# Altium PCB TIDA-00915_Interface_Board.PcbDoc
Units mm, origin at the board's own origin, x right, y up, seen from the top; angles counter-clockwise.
Board outline 75 x 27 mm, 4 copper layers (Top Layer, Signal Layer 1, Signal Layer 2, Bottom Layer), stack 0.8 mm thick; 16 components, 9 nets, 149 pads, 23 vias.
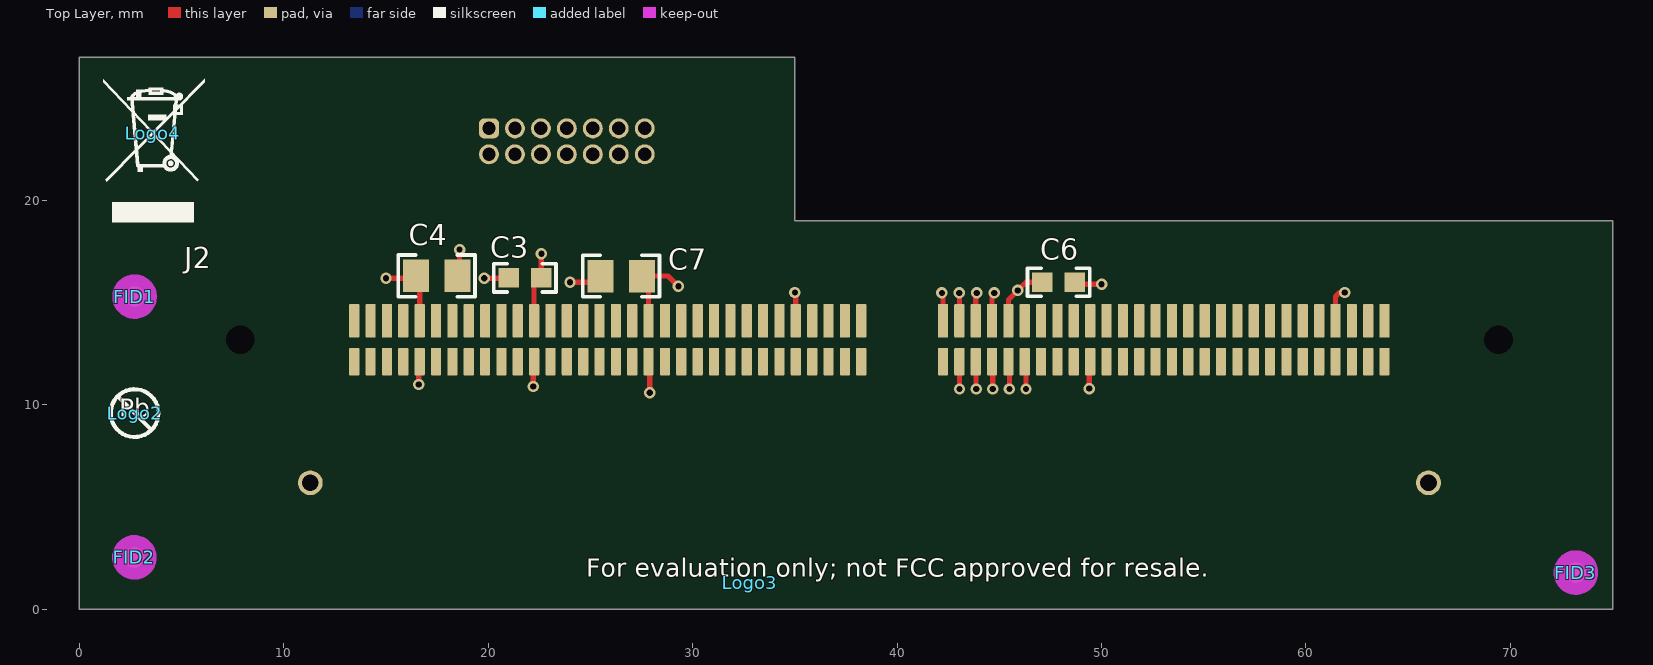
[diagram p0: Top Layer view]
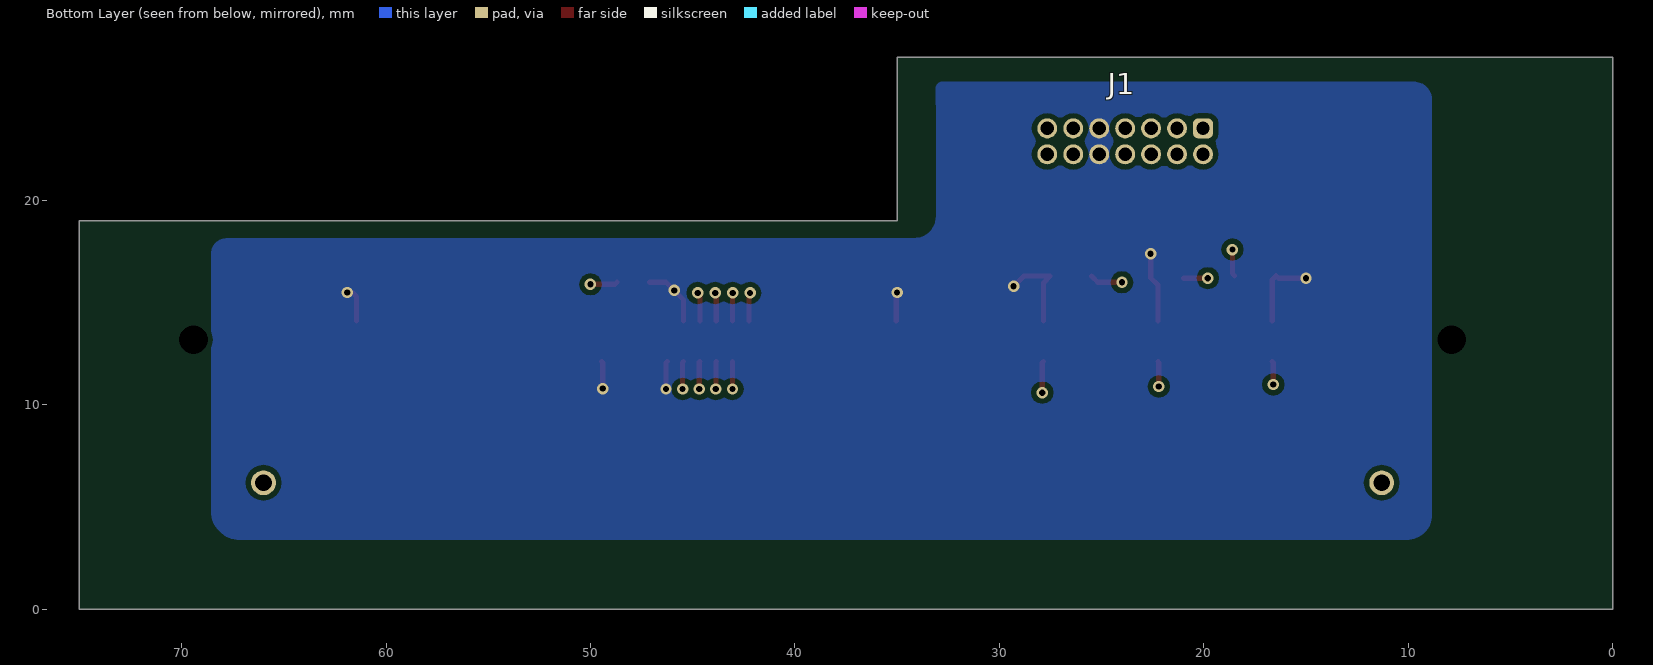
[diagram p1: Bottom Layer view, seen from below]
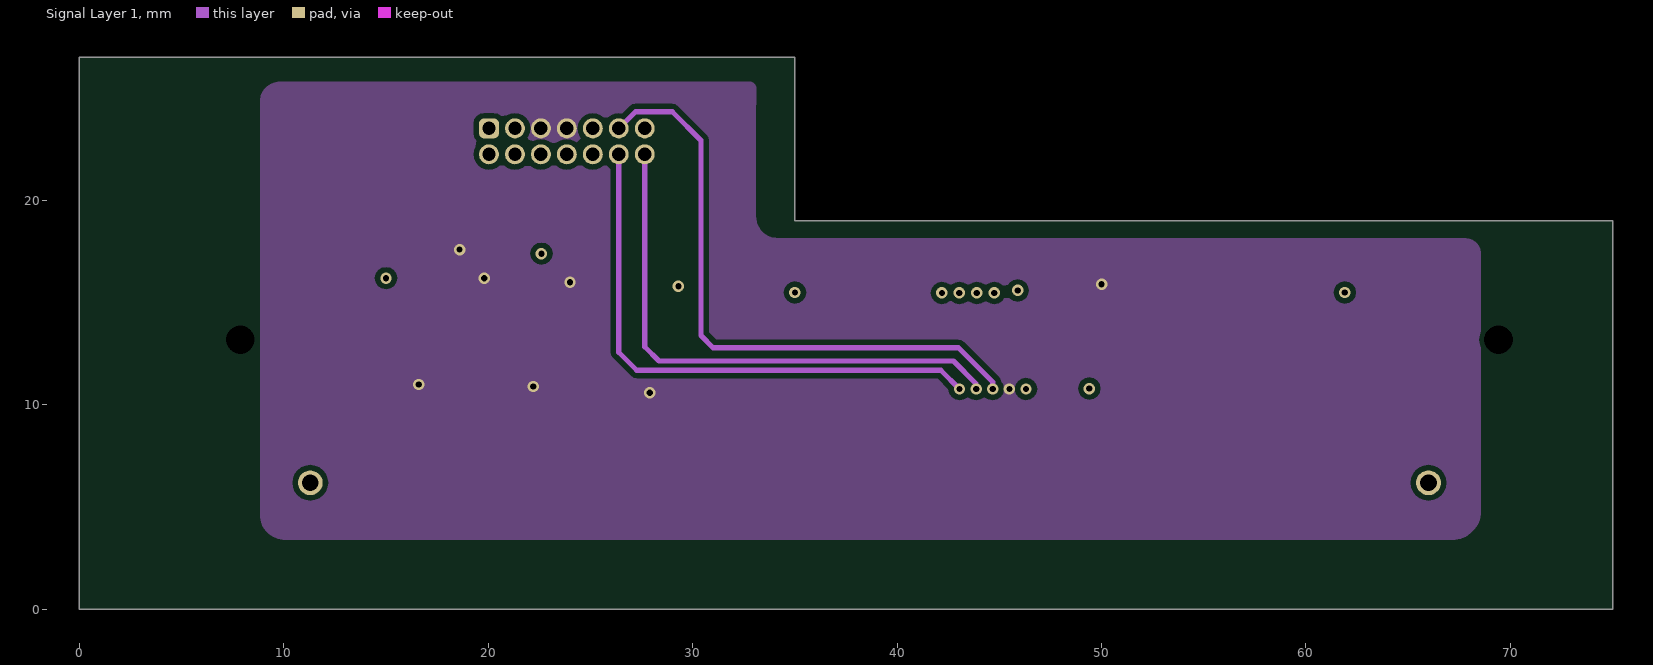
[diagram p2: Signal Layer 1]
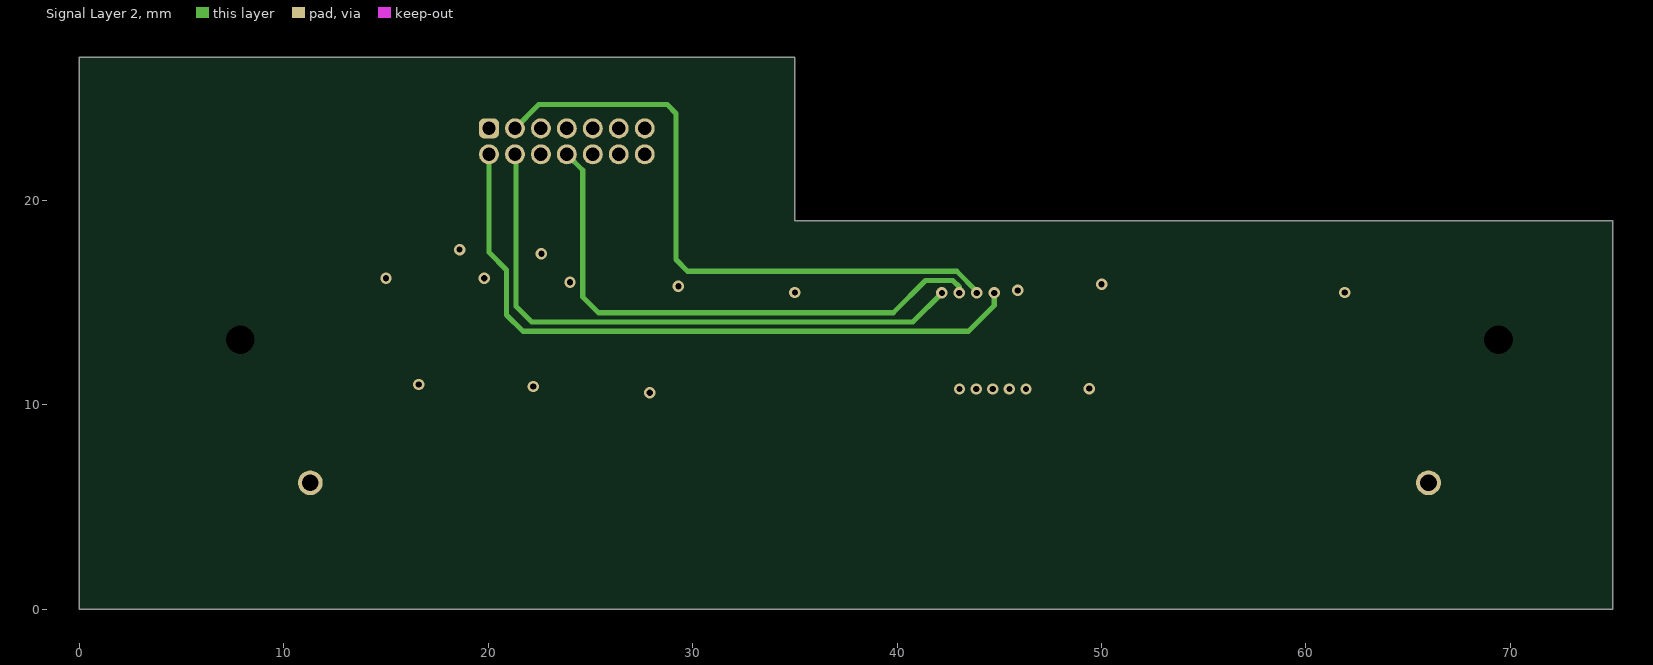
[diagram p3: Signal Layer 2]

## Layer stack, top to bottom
Top Solder: solder mask 0.0102, Solder Resist, Dk 3.5
Top Layer: signal copper 0.07
Dielectric 3: dielectric 0.16, FR-4  High Tg, Dk 4.2
Signal Layer 1: signal copper 0.07
Dielectric1: core 0.2, FR-4  High Tg, Dk 4.8
Signal Layer 2: signal copper 0.07
Dielectric 2: dielectric 0.16, FR-4  High Tg, Dk 4.2
Bottom Layer: signal copper 0.07
Bottom Solder: solder mask 0.0102, Solder Resist, Dk 3.5

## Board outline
0,0 75,0 75,19 35,19 35,27 0,27

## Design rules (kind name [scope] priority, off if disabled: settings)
AcuteAngle [All] p1: minimum=4.50000000000000E+0001 checktracksonly=FALSE
AssemblyTestPointUsage [All] p1: valid=2
BoardOutlineClearance BoardOutlineClearance_MountingHoles [OnCopper and InComponentClass('Mounting Holes')] p1: gap=1.016 ignorepadtopadclearanceinfootprint=FALSE
BoardOutlineClearance BoardOutlineClearance_Poly [OnCopper and IsPoly] p2: gap=0.635 ignorepadtopadclearanceinfootprint=FALSE
BoardOutlineClearance [OnCopper and Not InComponentClass('Logo') and not InComponentClass('FiducialMark') and not InRegion(1000,500,4000,800) and not InPoly] p3: gap=0.8 ignorepadtopadclearanceinfootprint=FALSE
Clearance Clearance_Keepouts [((IsTrack Or IsArc) And Not InPoly) And IsFree and IsKeepOut vs ((IsTrack Or IsArc) And Not InPoly) And IsFree and IsKeepOut] p1: gap=0 ignorepadtopadclearanceinfootprint=FALSE
Clearance Clearance_Poly [InPolygon] p2: gap=0.254 ignorepadtopadclearanceinfootprint=FALSE except(0: Arc-Hole Track-Hole SMDPad-Hole THPad-Hole Via-Hole Fill-Hole Poly-Hole Region-Hole Text-Hole)
Clearance Clearance_FiducialMark [IsKeepOut and InComponentClass('FiducialMark') vs IsPad and InComponentClass('FiducialMark')] p3: gap=0 ignorepadtopadclearanceinfootprint=FALSE
Clearance [All] p4: gap=0.2 ignorepadtopadclearanceinfootprint=FALSE except(0: Arc-Hole Track-Hole SMDPad-Hole THPad-Hole Via-Hole Fill-Hole Poly-Hole Region-Hole Text-Hole)
ComponentClearance ComponentClearance_MountingHoles_FiducialMarks [InComponentClass('Mounting Holes') vs InComponentClass('FiducialMark')] p1: gap=1.27 collisioncheckmode=3 verticalgap=0.254 showdistances=FALSE
ComponentClearance ComponentClearance_Shunt [InComponentClass('Header') vs InComponentClass('Shunt')] p2: gap=0 collisioncheckmode=3 verticalgap=0 showdistances=FALSE
ComponentClearance ComponentClearance_Logo [InComponentClass('Logo')] p3: gap=1.27 collisioncheckmode=3 verticalgap=0.254 showdistances=FALSE
ComponentClearance ComponentClearance_ScrewToNut [(HasFootprint('NY PMS 440 0025 PH')) vs (HasFootprint('Keystone_1902C'))] p4: gap=0.127 collisioncheckmode=3 verticalgap=0.254 showdistances=FALSE
ComponentClearance ComponentClearance_MountingHoles [InComponentClass('Mounting Holes')] p5: gap=6.35 collisioncheckmode=3 verticalgap=2540 showdistances=FALSE
ComponentClearance ComponentClearance_SmallPassives [HasFootprint('0201*') or HasFootprint('0402*') or HasFootprint('0508') or HasFootprint('0603*') or HasFootprint('0612') or HasFootprint('0805*') or HasFootprint('0815*') or HasFootprint('0830*') or HasFootprint('1206*') or HasFootprint('1210*') or HasFootprint('1808*') or HasFootprint('1812*') or HasFootprint('1825*') or HasFootprint('2010*') or HasFootprint('2220*') or HasFootprint('2225*') or HasFootprint('2512*') or HasFootprint('2728*') or HasFootprint('3518*') vs HasFootprint('0201*') or HasFootprint('0402*') or HasFootprint('0508') or HasFootprint('0603*') or HasFootprint('0612') or HasFootprint('0805*') or HasFootprint('0815*') or HasFootprint('0830*') or HasFootprint('1206*') or HasFootprint('1210*') or HasFootprint('1808*') or HasFootprint('1812*') or HasFootprint('1825*') or HasFootprint('2010*') or HasFootprint('2220*') or HasFootprint('2225*') or HasFootprint('2512*') or HasFootprint('2728*') or HasFootprint('3518*')] p6: gap=0.38 collisioncheckmode=3 verticalgap=0.254 showdistances=FALSE
ComponentClearance ComponentClearance_THtoSMT [IsThruComponent vs IsSMTComponent] p7: gap=0.508 collisioncheckmode=3 verticalgap=0.762 showdistances=FALSE
ComponentClearance ComponentClearance_THtoTH [IsThruComponent vs IsThruComponent] p8: gap=0.762 collisioncheckmode=3 verticalgap=0.762 showdistances=FALSE
ComponentClearance [All] p9: gap=0 collisioncheckmode=3 verticalgap=0 showdistances=FALSE
DiffPairsRouting [All] p1: maxlimit=2.54 minlimit=0.254 mostfreqgap=0.254 toplayer_minwidth=0.381 toplayer_maxwidth=0.381 toplayer_prefwidth=0.381 midlayer1_minwidth=0.381 midlayer1_maxwidth=0.381 midlayer1_prefwidth=0.381 midlayer2_minwidth=0.381 midlayer2_maxwidth=0.381 midlayer2_prefwidth=0.381 bottomlayer_minwidth=0.381 bottomlayer_maxwidth=0.381 bottomlayer_prefwidth=0.381 maxuncoupledlength=25.4
FabricationTestPointUsage TestPointUsage [All] p1: valid=2 allowmultiple=FALSE
FabricationTestpoint Testpoint [All] p1: side=3 testpointundercomponent=TRUE minsize=1.016 maxsize=2.54 preferedsize=1.524 minholesize=0 maxholesize=1.016 preferedholesize=0.813 testpointgrid=0.025 allowsidetop=TRUE allowsidebottom=TRUE usegrid=TRUE gridtolerance=0
FanoutControl Fanout_LCC [IsLCC] p1: bgadir=Out bgaviamode=Centered fanoutstyle=Auto fanoutdirection=Alternating viagrid=0.025 // Fanout_LCC (Default Rule)
FanoutControl Fanout_BGA [IsBGA] p2: bgadir=Out bgaviamode=Centered fanoutstyle=Auto fanoutdirection=Alternating viagrid=0.025 // Fanout_BGA (Default Rule)
FanoutControl Fanout_Default [All] p4: bgadir=Out bgaviamode=Centered fanoutstyle=Auto fanoutdirection=Alternating viagrid=0.025 // Fanout_Default (Default Rule)
FanoutControl Fanout_Small [(CompPinCount < 5)] p5: bgadir=Out bgaviamode=Centered fanoutstyle=Auto fanoutdirection=OutThenIn viagrid=0.025 // Fanout_Small (Default Rule)
HoleSize [All] p1: absolutevalues=TRUE maxlimit=6.375 minlimit=0.2 maxpercent=80.000 minpercent=20.000
MinimumAnnularRing MinimumAnnularRing_ThermalPadVias [IsVia and InAnyComponent] p1: minimumring=0.15
MinimumAnnularRing [All] p2: minimumring=0.127
MinimumSolderMaskSliver MinimumSolderMaskSliver_Logo [InComponentClass('Logo') vs InComponentClass('Logo')] p1: minsoldermaskwidth=0.018
MinimumSolderMaskSliver [All] p2: minsoldermaskwidth=0.1
PlaneConnect [All] p1: planeconnectstyle=Relief reliefexpansion=0.254 reliefentries=4 reliefconductorwidth=0.254 reliefairgap=0.254
PolygonConnect [All] p1: connectstyle=Direct reliefconductorwidth=0.254 reliefentries=4 polygonreliefangle="90 Angle" airgapwidth=0.254
RoutingVias ThermalPadVias [IsVia and InAnyComponent] p1: holewidth=0.2 width=0.5 viastyle="Through Hole" minholewidth=0.2 minwidth=0.5 maxholewidth=0.33 maxwidth=0.6
RoutingVias [All] p2: holewidth=0.406 width=0.864 viastyle="Through Hole" minholewidth=0.2 minwidth=0.508 maxholewidth=1.016 maxwidth=1.651
SilkToBoardRegionClearance [Not ((IsComment or IsDesignator) And (Hide <> 'False')) and not InRegion(1000,500,4000,800)] p1:
SilkToSilkClearance SilkToSilkClearance_Pb-FreeLogo [(HasFootprint('Pb-Free_Overlay_Medium') OR HasFootprint('Pb-Free_Overlay_Small')) vs (HasFootprint('Pb-Free_Overlay_Medium') OR HasFootprint('Pb-Free_Overlay_Small'))] p1: silktosilkclearance=0
SilkToSilkClearance [All] p2: silktosilkclearance=0.102
SilkToSolderMaskClearance SilkToComponentPadClearance [(IsPad or IsFill or IsRegion) and InAnycomponent] p1: minsilkscreentomaskgap=0.127 clearancetoexposedcopper=TRUE
SilkToSolderMaskClearance "Silk to Solder Mask Opening" [All] p2: minsilkscreentomaskgap=0.102 clearancetoexposedcopper=FALSE
SolderMaskExpansion [All] p1: expansion=0.05
Width [All] p1: maxlimit=2.54 minlimit=0.152 preferedwidth=0.254 checkconnectedcopper=TRUE
15 further rules are at their usual default settings.

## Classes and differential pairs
component class FiducialMark: FID1 FID2 FID3
component class EVM_Hardware: FID1 FID2 FID3 Logo2 Logo3 Logo4
component class Connector: C3 C4 C6 C7 J1 J2

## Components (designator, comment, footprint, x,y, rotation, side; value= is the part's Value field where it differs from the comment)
C3 "06035C104KAT2A" 0603 21.793,16.213 r0 top value=0.1uF
C4 "C2012X7R1V475K125AC" 0805_HV 17.475,16.315 r0 top value=4.7uF
C6 "06035C104KAT2A" 0603 47.9,16 r180 top value=0.1uF
C7 "C2012X7R1V475K125AC" 0805_HV 26.5,16.3 r180 top value=4.7uF
FID1 "Fiducial" Fiducial10-20 2.7,15.3 r0 top
FID2 "Fiducial" Fiducial10-20 2.692,2.54 r0 top
FID3 "Fiducial" Fiducial10-20 73.2,1.8 r0 top
J1 "20021311-00014T4LF" FCI_20021311-00014XXLF 23.845,22.892 r270 bottom
J2 "HSEC8-160-01-L-RA-BL" Samtec_HSEC8-160-01-x-RA-BL 38.645,13.192 r90 top locked
Logo2 "Pb-Free Symbol" Pb-Free_Overlay_Small 2.7,9.6 r0 top
Logo3 "FCC disclaimer" FCC_disclaimer 32.8,1.3 r0 top
Logo4 "WEEE logo" WEEE_Minimum 3.6,23.3 r0 top
ZZ1 "This Assembly Note is for PCB labels only" AssemblyNoteLabel -16.572,95.432 r0 top
ZZ2 "These assemblies are ESD sensitive, ESD precautions shall be observed." AssemblyNote 46.328,99.932 r0 top
ZZ3 "These assemblies must be clean and free from flux and all contaminants. Use of no clean flux is not acceptable." AssemblyNote 6.928,104.432 r0 top
ZZ4 "These assemblies must comply with workmanship standards IPC-A-610 Class 2, unless otherwise specified." AssemblyNote 15.228,108.932 r0 top

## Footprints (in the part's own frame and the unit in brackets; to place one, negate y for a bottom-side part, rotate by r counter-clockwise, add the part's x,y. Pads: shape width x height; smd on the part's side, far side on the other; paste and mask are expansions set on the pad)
0603 [mm] "0603 from SM-752 data"
  rect 1x0.95 smd: 1(-0.8,0) 2(0.8,0)
  silkscreen extent -1.52,-0.69 1.52,0.69, body extent -0.87,-0.47 0.87,0.47, height 1
0805_HV [mil] "0805 with 30mil clearance between pads"
  rect 50x63 smd: 1(-40,0) 2(40,0)
  silkscreen extent -74,-40 74,40, body extent -43,-29 43,29, height 57
AssemblyNote [mm] "Assembly Note"
AssemblyNoteLabel [mm] "Assembly Note for PCB Labels"
FCC_disclaimer [mm]
FCI_20021311-00014XXLF [mm] "Receptacle, 1.27mm, 7x2, TH"
  rrect50% 0.975x0.975 hole 0.65: 1(-0.635,3.81)
  round 0.975 hole 0.65: 2(0.635,3.81) 3(-0.635,2.54) 4(0.635,2.54) 5(-0.635,1.27) 6(0.635,1.27) 7(-0.635,0) 8(0.635,0) 9(-0.635,-1.27) 10(0.635,-1.27) 11(-0.635,-2.54) 12(0.635,-2.54) 13(-0.635,-3.81) 14(0.635,-3.81)
  body extent -1.5,-4.67 1.5,4.68, height 4.3
Fiducial10-20 [mm]
  round 1 smd mask+0.5: 1(0,0)
  Top Layer keep-out circle w1.178: c0,0 r0.5
Pb-Free_Overlay_Small [mm]
  silkscreen extent -1.16,-1.17 1.17,1.17
Samtec_HSEC8-160-01-x-RA-BL [mm] "Receptacle,  0.8mm, 60x2, SMT"
  rrect20% 1.35x0.5 smd mask+0.05: 1(-1.075,25.2) 3(-1.075,24.4) 5(-1.075,23.6) 7(-1.075,22.8) 9(-1.075,22) 11(-1.075,21.2) 13(-1.075,20.4) 15(-1.075,19.6) 17(-1.075,18.8) 19(-1.075,18) 21(-1.075,17.2) 23(-1.075,16.4) 25(-1.075,15.6) 27(-1.075,14.8) 29(-1.075,14) 31(-1.075,13.2) 33(-1.075,12.4) 35(-1.075,11.6) 37(-1.075,10.8) 39(-1.075,10) 41(-1.075,9.2) 43(-1.075,8.4) 45(-1.075,7.6) 47(-1.075,6.8) 49(-1.075,6) 51(-1.075,5.2) 53(-1.075,4.4) 55(-1.075,3.6) 57(-1.075,2.8) 59(-1.075,2) 61(-1.075,1.2) 63(-1.075,0.4) 65(-1.075,-3.6) 67(-1.075,-4.4) 69(-1.075,-5.2) 71(-1.075,-6) 73(-1.075,-6.8) 75(-1.075,-7.6) 77(-1.075,-8.4) 79(-1.075,-9.2) 81(-1.075,-10) 83(-1.075,-10.8) 85(-1.075,-11.6) 87(-1.075,-12.4) 89(-1.075,-13.2) 91(-1.075,-14) 93(-1.075,-14.8) 95(-1.075,-15.6) 97(-1.075,-16.4) 99(-1.075,-17.2) 101(-1.075,-18) 103(-1.075,-18.8) 105(-1.075,-19.6) 107(-1.075,-20.4) 109(-1.075,-21.2) 111(-1.075,-22) 113(-1.075,-22.8) 115(-1.075,-23.6) 117(-1.075,-24.4) 119(-1.075,-25.2)
  rrect20% 1.65x0.5 smd mask+0.05: 2(0.925,25.2) 4(0.925,24.4) 6(0.925,23.6) 8(0.925,22.8) 10(0.925,22) 12(0.925,21.2) 14(0.925,20.4) 16(0.925,19.6) 18(0.925,18.8) 20(0.925,18) 22(0.925,17.2) 24(0.925,16.4) 26(0.925,15.6) 28(0.925,14.8) 30(0.925,14) 32(0.925,13.2) 34(0.925,12.4) 36(0.925,11.6) 38(0.925,10.8) 40(0.925,10) 42(0.925,9.2) 44(0.925,8.4) 46(0.925,7.6) 48(0.925,6.8) 50(0.925,6) 52(0.925,5.2) 54(0.925,4.4) 56(0.925,3.6) 58(0.925,2.8) 60(0.925,2) 62(0.925,1.2) 64(0.925,0.4) 66(0.925,-3.6) 68(0.925,-4.4) 70(0.925,-5.2) 72(0.925,-6) 74(0.925,-6.8) 76(0.925,-7.6) 78(0.925,-8.4) 80(0.925,-9.2) 82(0.925,-10) 84(0.925,-10.8) 86(0.925,-11.6) 88(0.925,-12.4) 90(0.925,-13.2) 92(0.925,-14) 94(0.925,-14.8) 96(0.925,-15.6) 98(0.925,-16.4) 100(0.925,-17.2) 102(0.925,-18) 104(0.925,-18.8) 106(0.925,-19.6) 108(0.925,-20.4) 110(0.925,-21.2) 112(0.925,-22) 114(0.925,-22.8) 116(0.925,-23.6) 118(0.925,-24.4) 120(0.925,-25.2)
  round 1.1 hole 1.4 unplated mask+0.127: ALIGN1(0,30.775) ALIGN2(0,-30.775)
  round 1.215 hole 0.81: MH1(-7,27.35) MH2(-7,-27.35)
  body extent -12.9,-33.65 2.75,33.65, height 6.26
WEEE_Minimum [mm] "WEEElie bin"
  silkscreen extent -2.42,-4.38 2.52,2.65

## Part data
C3 C6: library part CMP-0006802-4, "CAP, CERM, 0.1 uF, 50 V, +/- 10%, X7R, 0603", Cap_Case=0603, Manufacturer=AVX, Supplier Part Number 1=478-5052-1-ND, TempCo=X7R, Tolerance_%=10%, Value1=Unknown, Value2=50V, ValueDisplayed=0.1uF
C4 C7: library part CMP-0007885-2, "CAP, CERM, 4.7 uF, 35 V, +/- 10%, X7R, 0805", Cap_Case=0805, Manufacturer=TDK, Supplier Part Number 1=445-7555-1-ND, TempCo=X7R, Tolerance_%=10%, Value1="0.002346 ohm", Value2=35V, ValueDisplayed=4.7uF
FID1 FID2 FID3: library part CMP-0077181-1, "Fiducial mark.  There is nothing to buy or mount.", Manufacturer=N/A
J1: library part CMP-0086231-1, "Receptacle, 1.27mm, 7x2, Gold, TH", Color=Black, Current_A=1A, Manufacturer=FCI, Voltage_V=125V
J2: library part CMP-0085713-1, "Receptacle, 0.8mm, 60x2, Gold with Tin tail, SMT", Color=Black, Manufacturer=Samtec
Logo2: library part CMP-0074839-1
Logo3: library part CMP-0074847-1, "FCC_disclaimer"
Logo4: library part CMP-0074769-1
ZZ1: library part CMP-0003616-3
ZZ2: library part CMP-0077236-1
ZZ3: library part CMP-0077237-1
ZZ4: library part CMP-0077238-1

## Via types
v1: diameter 0.559, hole 0.305, Top Layer to Bottom Layer, 23 vias

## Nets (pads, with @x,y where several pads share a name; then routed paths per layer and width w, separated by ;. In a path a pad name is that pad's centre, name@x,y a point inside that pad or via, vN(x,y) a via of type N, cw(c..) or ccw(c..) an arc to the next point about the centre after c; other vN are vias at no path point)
5V: C3.1 C4.2 C6.1 C7.2 J1.5 J1.7 J2.9 J2.23 J2.37 J2.73 | length 10.7
  Top Layer w0.254: v1(16.6,11) 16.6,12.072 J2.9 ; C4.2 18.6,16.424 v1(18.6,17.6) ; v1(19.8,16.2) 20.98,16.2 C3.1 ; v1(22.2,10.9) 22.2,12.072 J2.23 ; v1(24,16) 25.184,16 C7.2 ; J2.37 27.9,12.062 v1(27.9,10.6) ; J2.73 45.491,12.071 v1(45.491,10.778) ; C6.1 48.8,15.9 v1(50,15.9)
Bot_FET_U: J1.3 J2.70 | length 32.5
  Top Layer w0.254: J2.70 43.845,15.422 v1(43.9,15.477)
  Signal Layer 2 w0.254: J1.3 22.467,24.689 28.753,24.689 29.185,24.257 29.185,17.107 29.754,16.537 42.914,16.537 43.9,15.551 v1(43.9,15.477)
Bot_FET_V: J1.4 J2.66 | length 30.6
  Top Layer w0.254: v1(42.189,15.477) 42.245,15.421 J2.66
  Signal Layer 2 w0.254: J1.4 21.354,22.208 21.354,14.83 22.13,14.054 40.767,14.054 v1(42.189,15.477)
Bot_FET_W: J1.14 J2.69 | length 28.3
  Top Layer w0.254: J1.14@27.655,21.945 J1.14 ; J2.69 43.866,12.096 v1(43.866,10.778)
  Signal Layer 1 w0.254: J1.14 27.655,12.845 28.354,12.146 42.754,12.146 43.866,11.034 v1(43.866,10.778)
"GaN Fault": J1.12 J2.67 | length 28.4
  Top Layer w0.254: J2.67 43.053,12.109 v1(43.053,10.778)
  Signal Layer 1 w0.254: J1.12 26.385,12.575 27.268,11.692 42.139,11.692 v1(43.053,10.778)
GND: C3.2 C4.1 C6.2 C7.1 J1.9 J1.10 J2.10 J2.24 J2.38 J2.56 J2.74 J2.75 J2.83 J2.114 | length 20.4
  Top Layer w0.254: v1(15,16.2) 16.344,16.2 C4.1 16.645,16.129 J2.10 ; J2.24 22.245,15.865 C3.2 22.593,17.393 v1(22.6,17.4) ; J2.38 27.845,15.971 C7.1 28.8,16.3 v1(29.3,15.8) ; v1(35,15.5) 35.045,15.455 J2.56 ; J2.74 45.445,15.145 v1(45.9,15.6) 46.3,16 C6.2 ; J2.75 46.304,12.058 v1(46.304,10.778) ; v1(49.4,10.8) 49.4,12.072 J2.83 ; J2.114 61.445,15.299 61.646,15.5 v1(61.9,15.5)
Top_FET_U: J1.2 J2.72 | length 34.9
  Top Layer w0.254: J2.72 44.645,15.367 v1(44.755,15.477)
  Signal Layer 2 w0.254: J1.2 20.035,17.465 20.9,16.6 20.9,14.4 21.7,13.6 43.488,13.6 44.755,14.867 v1(44.755,15.477)
Top_FET_V: J1.8 J2.68 | length 28.5
  Top Layer w0.254: J2.68 v1(43.045,15.477)
  Signal Layer 2 w0.254: J1.8 24.625,21.477 24.625,15.275 25.392,14.508 39.808,14.508 41.383,16.083 42.726,16.083 43.045,15.764 v1(43.045,15.477)
Top_FET_W: J1.11 J2.71 | length 31.4
  Top Layer w0.254: J2.71 44.679,12.083 v1(44.679,10.778)
  Signal Layer 1 w0.254: J1.11 27.199,24.341 29,24.341 30.4,22.942 30.4,13.4 31,12.8 43,12.8 44.679,11.121 v1(44.679,10.778)
pads on no net: FID1.1 FID2.1 FID3.1 J1.1 J1.6 J1.13 J2.1 J2.2 J2.3 J2.4 J2.5 J2.6 J2.7 J2.8 J2.11 J2.12 J2.13 J2.14 J2.15 J2.16 J2.17 J2.18 J2.19 J2.20 J2.21 J2.22 J2.25 J2.26 J2.27 J2.28 J2.29 J2.30 J2.31 J2.32 J2.33 J2.34 J2.35 J2.36 J2.39 J2.40 J2.41 J2.42 J2.43 J2.44 J2.45 J2.46 J2.47 J2.48 J2.49 J2.50 J2.51 J2.52 J2.53 J2.54 J2.55 J2.57 J2.58 J2.59 J2.60 J2.61 J2.62 J2.63 J2.64 J2.65 J2.76 J2.77 J2.78 J2.79 J2.80 J2.81 J2.82 J2.84 J2.85 J2.86 J2.87 J2.88 J2.89 J2.90 J2.91 J2.92 J2.93 J2.94 J2.95 J2.96 J2.97 J2.98 J2.99 J2.100 J2.101 J2.102 J2.103 J2.104 J2.105 J2.106 J2.107 J2.108 J2.109 J2.110 J2.111 J2.112 J2.113 J2.115 J2.116 J2.117 J2.118 J2.119 J2.120 J2.ALIGN1 J2.ALIGN2 J2.MH1 J2.MH2
copper on no net: | length 0.3
  Top Layer w0.254: 19.809,23.301 20.035,23.527 ; 22.555,22.237 22.575,22.257

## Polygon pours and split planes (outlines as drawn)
GND on Bottom Layer "BOTTOM_LAYER_GND_P000" (solid, remove dead copper, pour order 0): 8.839,24.934 cw(c9.705,24.934) 9.705,25.8 32.8,25.8 cw(c32.8,25.5) 33.1,25.5 33.096,23.851 33.096,19.228 ccw(c34.163,19.228) 34.163,18.161 67.767,18.161 cw(c67.767,17.374) 68.555,17.374 68.555,4.801 cw(c67.158,4.801) 67.158,3.404 10.058,3.404 cw(c10.058,4.623) 8.839,4.623
5V on Signal Layer 1 "SIGNAL_LAYER_1_5V_P002" (solid, remove dead copper, pour order 2): 8.839,24.839 cw(c9.8,24.839) 9.8,25.8 32.8,25.8 cw(c32.8,25.5) 33.1,25.5 33.096,23.851 33.096,19.228 ccw(c34.163,19.228) 34.163,18.161 67.767,18.161 cw(c67.767,17.374) 68.555,17.374 68.555,4.801 cw(c67.158,4.801) 67.158,3.404 10.058,3.404 cw(c10.058,4.623) 8.839,4.623

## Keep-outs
Keep-Out Layer:
  text ".Layer_Name" at -18.999,-73.114 h1.52

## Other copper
Top Layer:
  text ".Layer_Name" at -18.999,-73.114 h1.52
Signal Layer 1:
  text "'.Layer_Name'" at -19.1,-73 h1.52
Signal Layer 2:
  text "'.Layer_Name'" at -19,-73 h1.52
Bottom Layer:
  text ".Layer_Name" at -18.999,-73.114 h1.52

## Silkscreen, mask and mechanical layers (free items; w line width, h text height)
Top Overlay:
  text ".Layer_Name" at -18.999,-73.114 h1.52
Bottom Overlay:
  text ".Layer_Name" at -18.999,-73.114 h1.52
Top Paste:
  text ".Layer_Name" at -18.999,-73.114 h1.52
Bottom Paste:
  text ".Layer_Name" at -18.999,-73.114 h1.52
Top Solder:
  text ".Layer_Name" at -18.999,-73.114 h1.52
  text ".Layer_Name" at -18.999,-73.114 h1.52
Bottom Solder:
  text ".Layer_Name" at -18.999,-73.114 h1.52
Drill Guide:
  text ".Layer_Name" at -18.999,-73.114 h1.52
M1 Board Outline:
  lines w0.254: 73.355,-0.525 73.381,-0.551 ; 75,-0.5 75,19 35,19 35,27 0,27 0,0 75,0
M2 Board Dimensions:
  rectangle: -30.48,-61.468 -20.955,-58.293
  rectangle: -33.655,-58.293 -30.48,-55.118
  lines w0.178: -33.655,-58.293 -8.255,-58.293 ; -30.48,-61.468 -30.48,-55.118 ; -27.305,-61.468 -27.305,-55.118 ; -20.955,-61.468 -20.955,-55.118 ; -14.605,-61.468 -14.605,-55.118 ; -33.655,-61.468 -33.655,-55.118 -8.255,-55.118 -8.255,-61.468 -33.655,-61.468
M3 3D STEP Top:
  text ".Layer_Name" at -18.999,-73.114 h1.52
M4 3D STEP Bottom:
  text ".Layer_Name" at -18.999,-73.114 h1.52
M5 Assembly Top:
  lines w0.254: -41.072,-74.934 126.568,-74.934 ; -41.072,-69.77 126.619,-69.77 ; -41.072,-64.605 -41.072,-80.099 60.655,-80.099 126.619,-80.099 126.619,-64.605 -41.059,-64.605 -41.059,-80.099 -1.041,-80.099 ; 21.539,-80.099 21.539,-64.605 ; 53.721,-69.77 53.721,-64.605 ; 75.057,-69.77 75.057,-64.605 ; 90.856,-80.264 90.856,-75.112
  text "COMPONENTS MARKED 'DNP' SHOULD NOT BE POPULATED." at -4.356,-59.398 h1.52
  text "ASSEMBLY VARIANT:" at -4.369,-62.332 h1.52
  text ".VariantName" at 21.946,-62.332 h1.52
  text "PCB VIEWED FROM TOP SIDE" at -39.459,-67.962 h1.52
  text "BOARD #:" at 23.444,-67.962 h1.52
  text ".PRJ_Number" at 37.3,-67.962 h1.52
  text "REV:" at 58.75,-67.962 h1.52
  text ".PCB_Rev" at 66.154,-67.962 h1.52
  text "SVN REV:" at 80.035,-67.962 h1.52
  text ".VersionControl_RevNumber" at 92.888,-67.962 h1.52
  text "TID #:" at 23.444,-73.127 h1.52
  text ".TID" at 37.3,-73.127 h1.52
  text "PLOT NAME =" at -39.459,-78.342 h1.52
  text ".plot_File_Name" at -18.999,-78.342 h1.52
  text "GENERATED    :" at 23.495,-78.342 h1.52
  text ".Print_Date" at 45.58,-78.342 h1.52
  text ".Print_Time" at 64.097,-78.342 h1.52
  text "TEXAS INSTRUMENTS" at 96.215,-78.342 h1.52
M6 Assembly Bottom:
  lines w0.254: -41.084,-69.782 126.606,-69.782 ; -41.034,-74.947 126.606,-74.947 ; -5.321,-80.277 -5.321,-75.125 ; 10.477,-69.782 10.477,-64.618 ; 31.813,-69.782 31.813,-64.618 ; 63.995,-80.112 63.995,-64.618 ; 86.576,-80.112 126.594,-80.112 126.594,-64.618 -41.084,-64.618 -41.084,-80.112 24.879,-80.112 126.606,-80.112 126.606,-64.618
  text "COMPONENTS MARKED 'DNP' SHOULD NOT BE POPULATED." at 121.336,-59.385 h1.52
  text ".VariantName" at 94.818,-62.332 h1.52
  text "ASSEMBLY VARIANT:" at 121.209,-62.332 h1.52
  text ".VersionControl_RevNumber" at -7.353,-67.975 h1.52
  text "SVN REV:" at 5.499,-67.975 h1.52
  text ".PCB_Rev" at 19.38,-67.975 h1.52
  text "REV:" at 26.784,-67.975 h1.52
  text ".PRJ_Number" at 48.235,-67.975 h1.52
  text "BOARD #:" at 62.09,-67.975 h1.52
  text "PCB VIEWED FROM BOTTOM SIDE" at 124.993,-67.975 h1.52
  text ".TID" at 48.235,-73.139 h1.52
  text "TID #:" at 62.09,-73.139 h1.52
  text "TEXAS INSTRUMENTS" at -10.681,-78.355 h1.52
  text ".Print_Time" at 21.438,-78.355 h1.52
  text ".Print_Date" at 39.954,-78.355 h1.52
  text "GENERATED    :" at 62.039,-78.355 h1.52
  text ".plot_File_Name" at 104.534,-78.355 h1.52
  text "PLOT NAME =" at 124.993,-78.355 h1.52
M9 Title Sheet:
  drawing of 57 lines, arcs and shapes, not listed
  text "1" at -14.863,152.819 h1.78
  text "2" at 48.527,152.819 h1.78
  text "3" at 111.756,152.819 h1.78
  text "4" at 175.425,152.819 h1.78
  text "5" at 238.9,152.819 h1.78
  text "6" at 302.527,152.819 h1.78
  text "A" at -44.234,123.787 h1.78
  text "A" at 331.686,123.787 h1.78
  text "B" at -44.234,63.335 h1.78
  text "B" at 331.686,63.335 h1.78
  text "C" at -44.234,3.01 h1.78
  text "C" at 331.686,3.01 h1.78
  text "PROJECT TITLE:" at 254.47,-44.259 h1.14
  text ".PRJ_Title" at 255.74,-47.646 h1.78
  text "DESIGNED FOR:" at 254.47,-51.905 h1.14
  text ".PRJ_Customer" at 255.74,-55.461 h1.78
  text "D" at -44.234,-57.188 h1.78
  text "D" at 331.686,-57.188 h1.78
  text "FILE NAME:" at 254.47,-59.525 h1.14
  text ".PCB_File_Name_No_Path" at 255.74,-62.573 h1.78
  text "Texas Instruments (TI) and/or its licensors do not warrant the accuracy or completeness of this specification" at 128.245,-66.684 h1.14
  text "ENGINEER:" at 254.47,-66.891 h1.14
  text "LAYOUT BY:" at 292.697,-66.891 h1.14
  text "or any information contained therein. TI and/or its licensors do not warrant that this design will meet" at 127.102,-69.545 h1.14
  text ".PRJ_Engineer" at 255.74,-70.828 h1.78
  text ".PCB_Layout" at 293.98,-70.828 h1.78
  text "the specifications, will be suitable for your application or fit for any particular purpose, or will operate in" at 127.102,-72.407 h1.14
  text "ALTIUM DESIGNER VERSION:" at 292.697,-74.765 h1.14
  text "an implementation. TI and/or its licensors do not warrant that the design is production worthy. You should" at 127.102,-75.269 h1.14
  text "completely validate and test your design implementation to confirm the system functionality for your application." at 128.245,-78.13 h1.14
  text ".print_Scale" at 255.74,-78.151 h1.78
  text ".Application_BuildNumber" at 293.98,-78.151 h1.78
  text "1" at -14.863,-83.401 h1.78
  text "2" at 48.527,-83.401 h1.78
  text "3" at 111.756,-83.401 h1.78
  text "4" at 175.425,-83.401 h1.78
  text "5" at 238.9,-83.401 h1.78
  text "6" at 302.527,-83.401 h1.78
M10 Fab Notes:
  drawing of 189 lines, arcs and shapes, not listed
  text "DESIGN INFORMATION" at 280.848,110.139 h1.52
  text "MIN. TRACK WIDTH:" at 264.476,106.783 h1.52
  text "8" at 292.321,106.783 h1.52
  text "MIL" at 296.252,106.783 h1.52
  text "MIN. CLEARANCE:" at 264.476,103.63 h1.52
  text "0.2" at 290.797,103.63 h1.52
  text "mm" at 296.252,103.63 h1.52
  text "MIN. VIA PAD SIZE:" at 264.476,100.477 h1.52
  text "24" at 291.559,100.477 h1.52
  text "MIL" at 296.252,100.477 h1.52
  text "0.05mm (2MIL)" at 282.129,97.178 h1.52
  text "MINIMUM ANNULAR RING" at 256.114,96.969 h1.52
  text "EXTERNAL" at 300.113,96.969 h1.52
  text "PER" at 261.194,94.172 h1.52
  text "IPC-D-275 CLASS 2 LEVEL C" at 266.782,94.172 h1.52
  text "MIL, HOLES" at 304.583,91.62 h1.52
  text "+/-" at 294.615,91.401 h1.52
  text "+/-" at 316.306,91.401 h1.52
  text "REGISTRATION TOLERANCES:" at 256.114,91.374 h1.52
  text "METAL" at 286.588,91.374 h1.52
  text "5" at 301.224,91.375 h1.52
  text "3" at 322.382,91.375 h1.52
  text "MIL" at 325.335,91.374 h1.52
  text "HOLE SIZE TOLERANCE (UNLESS OTHERWISE SPECIFIED):" at 256.114,88.877 h1.52
  text "+/-" at 316.306,88.804 h1.52
  text "3" at 322.382,88.777 h1.52
  text "MIL" at 325.335,88.777 h1.52
  text "MATERIAL:" at 254.215,85.281 h1.52
  text "FR-4 High Tg" at 279.271,82.016 h1.52
  text "X" at 275.602,81.814 h1.52
  text "FR-408" at 264.908,81.699 h1.52
  text "OTHER" at 302.703,81.699 h1.52
  text "62 MIL (1.6mm) +/-10%" at 273.039,78.066 h1.52
  text "X" at 269.988,78.004 h1.52
  text "THICKNESS:" at 256.114,77.857 h1.52
  text "OTHER" at 305.675,77.857 h1.52
  text "TOLERANCE:" at 256.114,74.344 h1.52
  text "X" at 277.659,74.344 h1.52
  text "ANSI IPC-6012 TYPE 3 CLASS 2" at 282.181,74.344 h1.52
  text "OTHER +/-" at 282.18,70.681 h1.52
  text "BOW & TWIST:" at 256.114,66.994 h1.52
  text "X" at 277.659,66.994 h1.52
  text "ANSI IPC-6012 TYPE 3 CLASS 2" at 282.181,66.994 h1.52
  text "OTHER +/-" at 282.18,63.268 h1.52
  text "DRILLING:" at 254.215,59.95 h1.52
  text "NC_DRILL FILES" at 298.944,57.278 h1.52
  text "REFERENCE:" at 256.114,57.178 h1.52
  text "X" at 272.808,57.176 h1.52
  text "AS SHOWN" at 277.329,57.178 h1.52
  text "X" at 295.693,57.178 h1.52
  text "OTHER" at 306.513,53.565 h1.52
  text "PTH COPPER THICKNESS:" at 256.106,53.475 h1.52
  text "X" at 285.042,53.475 h1.52
  text "20-30 um" at 288.293,53.475 h1.52
  text "BOARD FINISH:" at 254.215,49.726 h1.52
  text "SILKSCREEN:" at 258.157,46.929 h1.52
  text "X" at 282.485,46.929 h1.52
  text "TOP" at 285.457,46.929 h1.52
  text "X" at 295.439,46.929 h1.52
  text "BOTTOM" at 298.436,46.929 h1.52
  text "SILKSCREEN COLOR:" at 258.157,42.987 h1.52
  text "X" at 282.46,42.987 h1.52
  text "WHITE" at 285.457,42.987 h1.52
  text "OTHER" at 298.436,42.987 h1.52
  text "X" at 285.787,39.344 h1.52
  text "GREEN" at 288.784,39.344 h1.52
  text "OTHER" at 304.481,39.344 h1.52
  text "SOLDER RESIST COLOR:" at 258.157,39.169 h1.52
  text "X" at 285.787,35.426 h1.52
  text "MATTE" at 288.784,35.426 h1.52
  text "SEMI-GLOSS" at 304.47,35.409 h1.52
  text "IMMERSION GOLD (ENIG)" at 281.164,31.037 h1.52
  text "ENEPIG" at 315.138,30.854 h1.52
  text "SURFACE FINISH:" at 254.215,30.828 h1.52
  text "X" at 276.643,30.828 h1.52
  text "IMM. TIN/SILVER OR EQUIV" at 262.585,27.341 h1.52
  text "OTHER" at 298.944,27.241 h1.52
  text "ARRAY/PANEL:" at 254.215,23.294 h1.52
  text "X" at 276.74,23.232 h1.52
  text "CUT AND TRIM PER M1 BOARD OUTLINE" at 281.164,23.085 h1.52
  text "N.C. ROUTE" at 281.164,19.632 h1.52
  text "V. SCORE" at 303.161,19.632 h1.52
  text "CERTIFICATION:" at 254.215,16.352 h1.52
  text "MATERIALS AND WORKMANSHIP FOR ALL PCBS" at 272.63,16.352 h1.52
  text "TO MEET OR EXCEED THE REQUIREMENTS OF:" at 272.63,13.963 h1.52
  text "X" at 263.423,10.695 h1.52
  text "ANSI IPC-A-600F CLASS ->" at 266.674,10.695 h1.52
  text "X" at 308.533,10.695 h1.52
  text "2" at 311.327,10.695 h1.52
  text "1" at 303.326,10.657 h1.52
  text "3" at 320.318,10.657 h1.52
  text "X" at 284.047,6.944 h1.52
  text "RoHS" at 287.298,6.944 h1.52
  text "OTHER" at 303.666,6.944 h1.52
  text "PER ORDER" at 313.752,6.944 h1.52
  text "ALL BOARDS MUST MEET OR EXCEED UL94-V0 REQUIREMENTS." at 254.914,3.037 h1.52
  text "PCB MUST BEAR THE UL94V-0 UL REGISTERED MATERIAL ID NUMBER" at 254.914,0.089 h1.52
  text "ADDITIONAL REQUIREMENTS:" at 254.215,-4.214 h1.52
  text "MICROSECTION:" at 256.114,-6.935 h1.52
  text "YES" at 279.12,-6.935 h1.52
  text "NOTE:" at 101.412,-8.018 h1.52
  text "REQUIRED" at 301.002,-10.601 h1.52
  text "BARE BOARD ELEC. TEST:" at 256.114,-10.674 h1.52
  text "NONE" at 289.28,-10.674 h1.52
  text "X" at 298.005,-10.674 h1.52
  text "PER ORDER" at 316.038,-10.674 h1.52
  text "1)THIS IS NOT AN IMPEDANCE CONTROLLED BOARD" at 99.5,-11.6 h1.52
  text "2)ALL VIAS ARE NONTENTED." at 99.331,-14.522 h1.52
  text "XX MIL VIAS REQUIRE NON-CONDUCTIVE FILL AND PLANARIZE" at 260.385,-15.88 h1.5
  text "3)SELECTION OF DIELECRIC THICKNESS IS UP TO FAB VENDOR." at 99.431,-17.422 h1.52
  text "XX MIL VIAS REQUIRE CONDUCTIVE FILL AND PLANARIZE" at 260.588,-18.521 h1.52
  text "4)COPPER THICKNESS SHOULD BE 2 OZ FOR INTERNAL AND EXTERNAL LAYERS." at 99.531,-20.422 h1.52
  text "OUTER XX MIL TRACES REQUIRE 50 OHM SINGLE-ENDED IMPEDANCE" at 260.563,-22.671 h1.47
  text "LAYER 2 & 3 (INNER LAYERS) XX MIL WIDE, XX MIL SPACE / TRACES REQUIRE 100 OHM DIFFERENTIAL IMPEDANCE" at 260.36,-28.658 h1.52
M11 Gerber Information:
  lines w0.254: -41.072,-74.934 126.568,-74.934 ; -41.072,-69.77 126.619,-69.77 ; -41.072,-64.605 -41.072,-80.099 60.655,-80.099 126.619,-80.099 126.619,-64.605 -41.059,-64.605 -41.059,-80.099 -1.041,-80.099 ; 21.539,-80.099 21.539,-64.605 ; 53.721,-69.77 53.721,-64.605 ; 75.057,-69.77 75.057,-64.605 ; 90.856,-80.264 90.856,-75.112
  text "ALL ARTWORK VIEWED FROM TOP SIDE" at -39.459,-67.962 h1.52
  text "BOARD #:" at 23.444,-67.962 h1.52
  text ".PRJ_Number" at 37.3,-67.962 h1.52
  text "REV:" at 58.75,-67.962 h1.52
  text ".PCB_Rev" at 66.154,-67.962 h1.52
  text "SVN REV:" at 80.035,-67.962 h1.52
  text ".VersionControl_RevNumber" at 92.888,-67.962 h1.52
  text "LAYER NAME =" at -39.459,-73.114 h1.52
  text "TID #:" at 23.444,-73.127 h1.52
  text ".TID" at 37.3,-73.127 h1.52
  text "PLOT NAME =" at -39.459,-78.342 h1.52
  text ".plot_File_Name" at -18.999,-78.342 h1.52
  text "GENERATED    :" at 23.495,-78.342 h1.52
  text ".Print_Date" at 45.58,-78.342 h1.52
  text ".Print_Time" at 64.097,-78.342 h1.52
  text "TEXAS INSTRUMENTS" at 96.215,-78.342 h1.52
M12 Stackup:
  drawing of 295 lines, arcs and shapes, not listed
  text "Layer" at 215.21,147.574 h1.52
  text "Name" at 225.622,147.574 h1.52
  text "Material" at 249.491,147.574 h1.52
  text "Thickness" at 272.091,147.574 h1.52
  text "Constant" at 288.597,147.574 h1.52
  text "Board Layer Stack" at 303.072,147.574 h1.52
  text "1" at 215.21,144.526 h1.52
  text "Top Overlay" at 225.622,144.526 h1.52
  text "2" at 215.21,141.478 h1.52
  text "Top Solder" at 225.622,141.478 h1.52
  text "Solder Resist" at 249.491,141.478 h1.52
  text "0.40mil" at 272.091,141.478 h1.52
  text "3.5" at 288.597,141.478 h1.52
  text "3" at 215.21,138.43 h1.52
  text "Top Layer" at 225.622,138.43 h1.52
  text "Copper" at 249.491,138.43 h1.52
  text "2.76mil" at 272.091,138.43 h1.52
  text "4" at 215.21,135.382 h1.52
  text "Dielectric 3" at 225.622,135.382 h1.52
  text "FR-4  High Tg" at 249.491,135.382 h1.52
  text "6.30mil" at 272.091,135.382 h1.52
  text "4.2" at 288.597,135.382 h1.52
  text "5" at 215.21,132.334 h1.52
  text "Signal Layer 1" at 225.622,132.334 h1.52
  text "Copper" at 249.491,132.334 h1.52
  text "2.76mil" at 272.091,132.334 h1.52
  text "6" at 215.21,129.286 h1.52
  text "Dielectric1" at 225.622,129.286 h1.52
  text "FR-4  High Tg" at 249.491,129.286 h1.52
  text "7.87mil" at 272.091,129.286 h1.52
  text "4.8" at 288.597,129.286 h1.52
  text "7" at 215.21,126.238 h1.52
  text "Signal Layer 2" at 225.622,126.238 h1.52
  text "Copper" at 249.491,126.238 h1.52
  text "2.76mil" at 272.091,126.238 h1.52
  text "8" at 215.21,123.19 h1.52
  text "Dielectric 2" at 225.622,123.19 h1.52
  text "FR-4  High Tg" at 249.491,123.19 h1.52
  text "6.30mil" at 272.091,123.19 h1.52
  text "4.2" at 288.597,123.19 h1.52
  text "9" at 215.21,120.142 h1.52
  text "Bottom Layer" at 225.622,120.142 h1.52
  text "Copper" at 249.491,120.142 h1.52
  text "2.76mil" at 272.091,120.142 h1.52
  text "10" at 215.21,117.094 h1.52
  text "Bottom Solder" at 225.622,117.094 h1.52
  text "Solder Resist" at 249.491,117.094 h1.52
  text "0.40mil" at 272.091,117.094 h1.52
  text "3.5" at 288.597,117.094 h1.52
  text "11" at 215.21,114.046 h1.52
  text "Bottom Overlay" at 225.622,114.046 h1.52
M14 Component Bodies Bottom:
  text ".Layer_Name" at -18.999,-73.114 h1.52
M15 Courtyards Top:
  text ".Layer_Name" at -18.999,-73.114 h1.52
M16 Courtyards Bottom:
  text ".Layer_Name" at -18.999,-73.114 h1.52
Drill Drawing:
  circle w0.254: c102.583,31.656 r0.702
  lines w0.254: 101.882,22.884 103.285,22.884 102.583,21.481 101.882,22.884 ; 101.882,24.989 102.233,24.989 102.583,24.638 102.934,24.989 103.285,24.989 102.934,25.34 103.285,25.691 102.934,25.691 102.583,26.042 102.233,25.691 101.882,25.691 102.233,25.34 101.882,24.989 ; 101.882,27.796 102.583,28.147 103.285,27.796 102.934,28.498 103.285,29.2 102.583,28.849 101.882,29.2 102.233,28.498 101.882,27.796
  lines w0.305: 100.609,20.533 169.249,20.533 ; 100.609,33.164 169.249,33.164 ; 109.191,17.376 109.191,36.322 ; 117.624,17.376 117.624,36.322 ; 133.793,17.376 133.793,36.322 ; 140.375,17.376 140.375,36.322 ; 149.904,17.376 149.904,36.322 ; 100.609,17.376 169.249,17.376 169.249,36.322 100.609,36.322 100.609,17.376
  text "Symbol" at 102.504,34.112 h1.83
  text "Quantity" at 110.138,34.112 h1.83
  text "Finished Hole Size" at 118.571,34.112 h1.83
  text "Plated" at 134.74,34.112 h1.83
  text "Hole Type" at 141.322,34.112 h1.83
  text "Drill Layer Pair" at 150.851,34.112 h1.83
  text "23" at 110.138,30.954 h1.52
  text "12.00mil (0.305mm)" at 118.571,30.954 h1.52
  text "PTH" at 134.74,30.954 h1.52
  text "Round" at 141.322,30.954 h1.52
  text "Top Layer - Bottom Layer" at 150.851,30.954 h1.52
  text "14" at 110.138,27.796 h1.52
  text "25.59mil (0.650mm)" at 118.571,27.796 h1.52
  text "PTH" at 134.74,27.796 h1.52
  text "Round" at 141.322,27.796 h1.52
  text "Top Layer - Bottom Layer" at 150.851,27.796 h1.52
  text "2" at 110.138,24.638 h1.52
  text "31.89mil (0.810mm)" at 118.571,24.638 h1.52
  text "PTH" at 134.74,24.638 h1.52
  text "Round" at 141.322,24.638 h1.52
  text "Top Layer - Bottom Layer" at 150.851,24.638 h1.52
  text "2" at 110.138,21.481 h1.52
  text "55.12mil (1.400mm)" at 118.571,21.481 h1.52
  text "NPTH" at 134.74,21.481 h1.52
  text "Round" at 141.322,21.481 h1.52
  text "Top Layer - Bottom Layer" at 150.851,21.481 h1.52
  text "41 Total" at 110.138,18.323 h1.52
  text "DRILL TOLERANCE" at 101.717,12.124 h1.52
  text "FOR 12MIL DRILL +0/- 12 MIL" at 103.901,3.971 h1.52
  text "FOR PTH +/- 3 MIL" at 103.774,0.872 h1.52
  text "FOR NPTH +/- 2 MIL" at 103.574,-2.328 h1.52
  text ".Layer_Name" at -18.999,-73.114 h1.52
M17 Embedded Cavity:
  text ".Layer_Name" at -18.999,-73.114 h1.52
M18 Embedded Assembly:
  text ".Layer_Name" at -18.999,-73.114 h1.52
M19 Embedded Keepout:
  text ".Layer_Name" at -18.999,-73.114 h1.52

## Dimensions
35,27 to 35,19 on M2 Board Dimensions
0,27 to 35,27 on M2 Board Dimensions
75,0 to 0,0 on M2 Board Dimensions
0,27 to 0,0 on M2 Board Dimensions
-33.655,-61.468 to -8.255,-61.468 on M2 Board Dimensions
